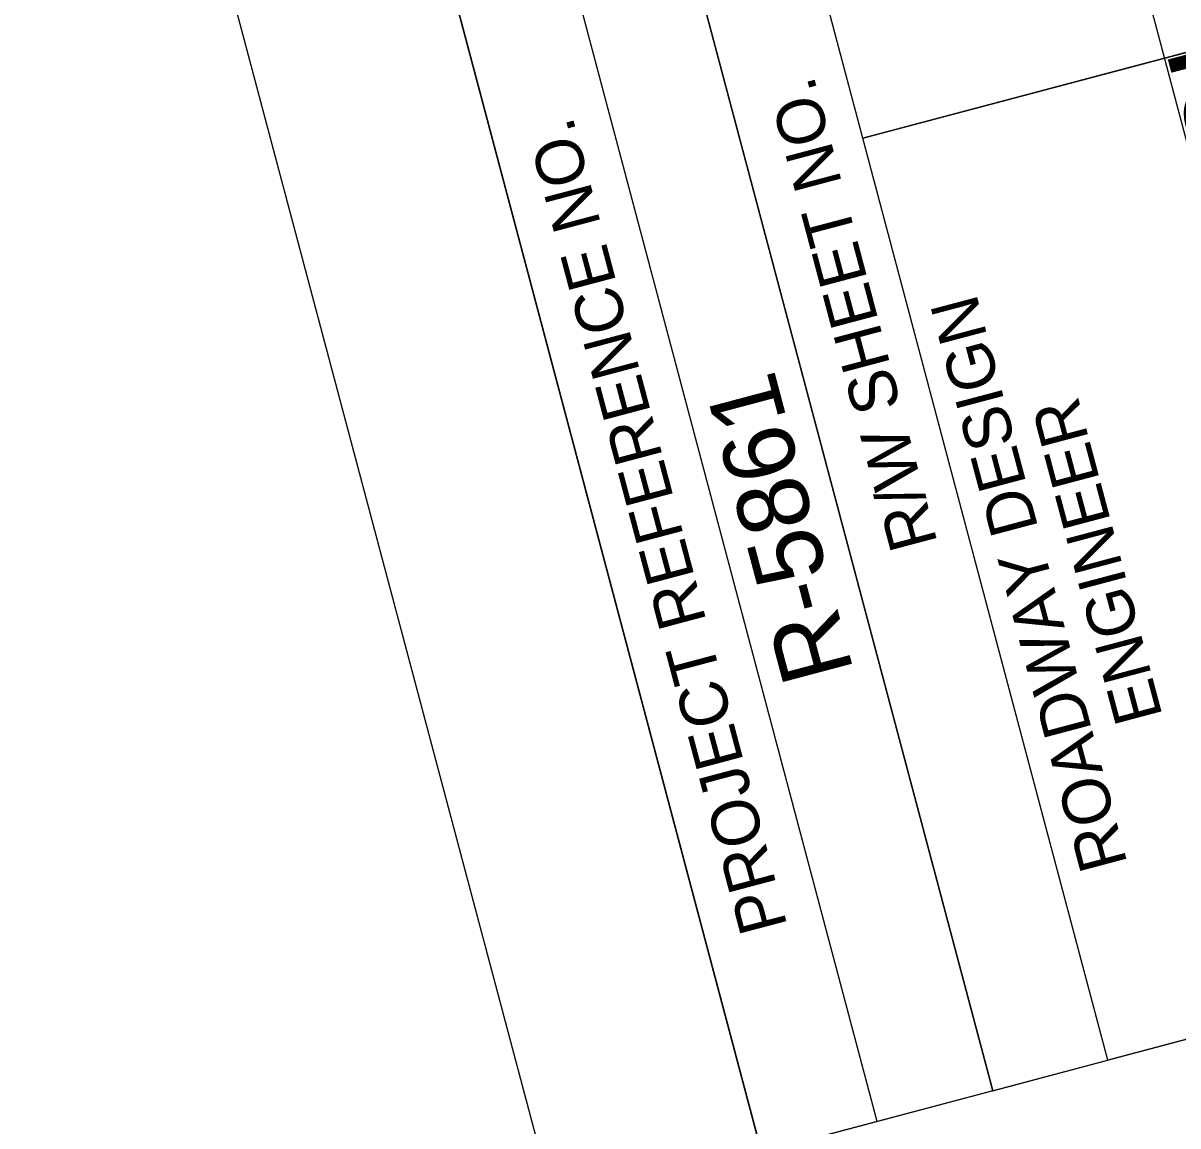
# Model space of a CAD drawing. Extents: x 473963 to 475454, y 503101 to 505009.
# Drawn here: x 473963.3 to 474084.4, y 504526.5 to 504642.2 of the extents above; entities that cross this region are included whole.
import ezdxf

# ---------------------------------------------------------------- set-up
doc = ezdxf.new("R2010")
doc.units = 0
for name, color, linetype in [('Pattern 18', 7, 'Continuous'), ('Prop PHM Label Text', 7, 'Continuous'), ('Scratch_Level_2', 7, 'Continuous'), ('Scratch_Level_3', 7, 'Continuous'), ('Scratch_Level_5', 7, 'Continuous')]:
    doc.layers.add(name, color=color, linetype=linetype)

msp = doc.modelspace()

# ---------------------------------------------------------------- linework, layer by layer
at = {"layer": 'Prop PHM Label Text'}
for p, q in [((474065.02, 504530.23), (474013.63, 504723.56)), ((474065.02, 504530.23), (474013.63, 504723.56)), ((474052.91, 504527), (474001.55, 504720.35)), ((474051.4, 504630.13), (474160.09, 504659.02)), ((474065.02, 504530.23), (474077.09, 504533.44))]:
    msp.add_line(p, q, dxfattribs=at)
for points in [[(473989.41, 504717.16), (474374.56, 503267.41), (475389.36, 503537.01), (475004.22, 504986.73)], [(474051.4, 504630.13), (474025.72, 504726.76), (474134.45, 504755.67), (474160.14, 504659.02)], [(474040.77, 504523.79), (473989.41, 504717.16), (474013.63, 504723.56), (474065.02, 504530.23)], [(474077.09, 504533.44), (474051.4, 504630.13), (474160.14, 504659.02), (474185.8, 504562.33)]]:
    msp.add_lwpolyline(points, close=True, dxfattribs=at)
at = {"layer": 'Scratch_Level_2'}
msp.add_lwpolyline([(474124.64, 504573.54), (474101.92, 504567.51), (474064.18, 504709.58), (474086.89, 504715.61)], close=True, dxfattribs=at)
at = {"layer": 'Scratch_Level_3'}
msp.add_lwpolyline([(474208.51, 504568.36), (474040.77, 504523.79), (474374.56, 503267.41), (474519.96, 503309.11), (474623.56, 503336.71), (475286.29, 503799.04), (475314.26, 503819.99), (475048.01, 504821.89), (474956.23, 504797.22), (474937.14, 504862.2), (474844.96, 504732.81), (474844.96, 504732.81), (474213.57, 504656.41)], close=True, dxfattribs=at)
at = {"layer": 'Scratch_Level_5'}
msp.add_lwpolyline([(475453.87, 503381.88), (475021.61, 505008.94), (473963.32, 504727.79), (474395.58, 503100.73)], close=True, dxfattribs=at)

# ---------------------------------------------------------------- texts
at = {"layer": 'Pattern 18'}
msp.add_text('R-5861', height=7.5, rotation=104.8779, dxfattribs=at).set_placement((474050.47, 504574.23))
at = {"layer": 'Prop PHM Label Text'}
for s, height, p in [('R/W SHEET NO.', 5.0001, (474059.26, 504587.68)), ('PROJECT REFERENCE NO.', 5.0001, (474043.51, 504547.49)), ('ROADWAY DESIGN', 5.0001, (474079.17, 504554.04)), ('ENGINEER', 5, (474082.86, 504569.49))]:
    msp.add_text(s, height=height, rotation=104.8779, dxfattribs=at).set_placement(p)
at = {"layer": 'Scratch_Level_2'}
for s, height, p in [('INCOMPLETE PLANS', 11.52, (474111.03, 504579.19)), ('DO NOT USE FOR R/W ACQUISITION', 5.76, (474116.91, 504584.11))]:
    msp.add_text(s, height=height, rotation=104.8779, dxfattribs=at).set_placement(p)

doc.saveas('drawing.dxf')
